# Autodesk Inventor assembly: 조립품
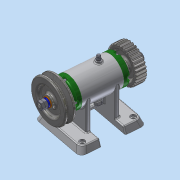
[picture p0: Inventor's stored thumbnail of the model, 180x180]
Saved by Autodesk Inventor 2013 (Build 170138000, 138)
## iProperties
Created: 2016-07
Part Number: 조립품
Document SubType Name: Assembly
Designer: dgall
Author: dgall
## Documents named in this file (15)
- C:\Users\dgall\Desktop\460707V1019\조립품.iam
- C:\Users\dgall\Desktop\460707V1019\V벨트풀리.ipt
- C:\Users\dgall\Desktop\460707V1019\너트 M 8.ipt
- C:\Users\dgall\Desktop\460707V1019\니플 M 6 x 0.75.ipt
- C:\Users\dgall\Desktop\460707V1019\베어링 15 x 32 x 9.ipt
- C:\Users\dgall\Desktop\460707V1019\본체.ipt
- C:\Users\dgall\Desktop\460707V1019\볼트 M 6 x 8.ipt
- C:\Users\dgall\Desktop\460707V1019\볼트 M4 x 12.ipt
- C:\Users\dgall\Desktop\460707V1019\스퍼기어.ipt
- C:\Users\dgall\Desktop\460707V1019\스프링와셔 8.ipt
- C:\Users\dgall\Desktop\460707V1019\오일 실 15 25 7.ipt
- C:\Users\dgall\Desktop\460707V1019\와셔 8x17.ipt
- C:\Users\dgall\Desktop\460707V1019\축.ipt
- C:\Users\dgall\Desktop\460707V1019\커버.ipt
- C:\Users\dgall\Desktop\460707V1019\키 3 x 3 x 12.ipt
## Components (11 placed, 3 different names)
1. V벨트풀리:1
2. KS B 2023 6002 - 15 x 32 x 9:1
3. KS B 2023 6002 - 15 x 32 x 9:2
4. ISO 4762 M4 x 12:2
5. ISO 4762 M4 x 12:3
6. ISO 4762 M4 x 12:4
7. ISO 4762 M4 x 12:5
8. ISO 4762 M4 x 12:1
9. ISO 4762 M4 x 12:6
10. ISO 4762 M4 x 12:7
11. ISO 4762 M4 x 12:8
